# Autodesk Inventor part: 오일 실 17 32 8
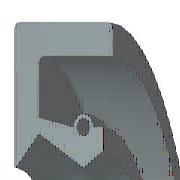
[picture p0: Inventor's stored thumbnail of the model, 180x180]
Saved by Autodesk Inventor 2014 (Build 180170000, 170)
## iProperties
IsCustomPart: 1
Created: 2012-02
Part Number: 오일 실 17 32 8
Material: 고무
Description: 오일-실
Document SubType Name: Modeling
Standard: KS B 2804
Designer: mduedu
Standards Organization: KS
Language: ko-KR
Size Designation: D - 17 32 8
Categories: <MemberInstance><Categories><Category DisplayName="샤프트 부품" InternalName="7f7aeb1f-a693-4053-b835-cee3144e0d98" Mnemonic="SHFT"><Category DisplayName="실링" Intern
Density: 0.93 g/cm^3
Appearance: 고무 - 검은색 - 버전 1.1
Mass: 2.28027 g
Surface Area: 32.1224 cm^2
Volume: 2.45191 cm^3
Author: mduedu
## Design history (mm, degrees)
revolve "본체" stored, may be unused: angle "d17" = 90 deg
revolve "스프링1" stored, may be unused: angle "d18" = 90 deg
body "Solid1"
sketch "스케치1"
  geometry: L1 (0, 16)-(8, 16); L2 (8, 14.25)-(1.75, 14.25); L3 (1.75, 10.25)-(4.9, 8.5); L4 (4.9, 8.5)-(0, 8.5); L5 (0, 0)-(9.586, 0) reference; L6 (4.9, 8.5)-(6.3, 9.375); L7 (0, 18)-(0, -3) reference; L8 (-1.941, 0)-(11.507, 0) reference; L9 (4.2, 10.6)-(1.75, 11.21); L10 (1.75, 11.21)-(1.75, 14.25); L11 (0, 16)-(0, 8.588); L12 (4.9, 8.5)-(0, 8.5); L13 (1.75, 10.25)-(0.152, 8.528); L14 (8, 16)-(8, 14.25); L15 (5.6, 10.6)-(6.3, 10.6); L16 (6.3, 10.6)-(6.3, 9.375); C1 r 0.455 at (4.9, 10.6); A1 r 0.7 centre (4.9, 10.6) between (5.6, 10.6) and (4.2, 10.6); A2 r 0.088 centre (0.088, 8.588) between (0, 8.588) and (0.152, 8.528); 1 further point
  constraints: 28 end point, 5 horizontal alignment, 5 point on line, 4 point on circle, 4 vertical alignment, 3 centre point, 3 tangent, 2 collinear, 2 horizontal, 2 perpendicular, 1 coincident, 1 parallel
  dimensions: "d0" = 32 diameter of L1 L5 (= SD2); "d1" = 1.75 distance of L1.end L2.start (= SD); "d2" = 0.91 diameter of C1 (= SPDI); "d3" = 1.4 diameter of A1 (= SPDA); "d4" = 17 diameter of L3.end L5 (= NND); "d5" = 20.5 diameter of L3.start L5 (= TKDM); "d7" = 22.42 diameter of L9.end L5 (= TKDM + 0.24 x SWDT); "d8" = 1.75 distance between parallel lines of L11 L10 (= SD); "d9" = 4.9 distance from line of L11 C1.centre (= SPDST); "d10" = 21.2 diameter of C1.centre L5 (= HLDM); "d11" = 0.0875 radius of A2 (= 0.25 x LAB); "d12" = 6.3 distance between parallel lines of L11 L16 (= SDI); "d13" = 18.75 diameter of L6.end L5 (= ABDM); "d14" = 8 distance from line of L11 L1.end (= SWDT)
fillet "모깎기1" dims "d6" = 0.3 (= RR)
other parameters: "SD2" = 32 [user parameter; used in 1 equation term], "SWDT" = 8 [user parameter; used in 2 equation terms], "RR" = 0.3 [user parameter; used in 1 equation term], "SD" = 1.75 [user parameter; used in 2 equation terms], "NND" = 17 [user parameter; used in 1 equation term], "SPDA" = 1.4 [user parameter; used in 1 equation term], "SPDI" = 0.91 [user parameter; used in 1 equation term], "TKDM" = 20.5 [user parameter; used in 2 equation terms], "HLDM" = 21.2 [user parameter; used in 1 equation term], "ABDM" = 18.75 [user parameter; used in 1 equation term], "SDI" = 6.3 [user parameter; used in 1 equation term], "SPDST" = 4.9 [user parameter; used in 1 equation term], "LAB" = 0.35 [user parameter; used in 1 equation term], "d15" = 0, "d16" = 0, "d19" = 0
